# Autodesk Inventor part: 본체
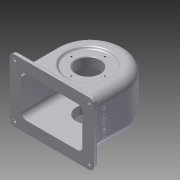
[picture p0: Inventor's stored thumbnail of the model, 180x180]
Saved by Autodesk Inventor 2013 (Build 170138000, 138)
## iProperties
Created: 2016-01
Part Number: 본체
Material: 알루미늄 6061
Document SubType Name: Modeling
Designer: dgall
Density: 2.71 g/cm^3
Mass: 810.796 g
Surface Area: 993.285 cm^2
Volume: 299.187 cm^3
Author: dgall
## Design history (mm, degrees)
sketch "스케치1"
  geometry: L1 (-57, 0)-(-57, -64); L2 (57, 0)-(57, -64); L3 (57, -64)-(-57, -64); A1 r 57 centre (0, 0) between (57, 0) and (-57, 0); 1 further point
  constraints: 6 end point, 2 point on circle, 2 tangent, 1 centre point, 1 coincident, 1 parallel, 1 perpendicular, 1 vertical
  dimensions: "d0" = 114 diameter of A1; "d2" = 64 distance of L1.start L1.end
extrude "돌출1" new body sketch "스케치1" stored distance "d3" = 77; taper "d4" = 0 deg
node "작업 평면1"
sketch "스케치2"
  geometry: L1 (57, 0)-(57, -64) reference; L2 (57, -64)-(-57, -64) reference; L3 (-57, -64)-(-57, 0) reference; L4 (-51, 0)-(-51, -64); L5 (51, 0)-(51, -64); A1 r 57 centre (0, 0) between (57, 0) and (-57, 0) reference; A2 r 51 centre (0, 0) between (51, 0) and (-51, 0); 1 further point
  constraints: 4 end point, 2 perpendicular, 2 point on circle, 2 point on line, 2 tangent, 1 centre point, 1 coincident
  dimensions: "d5" = 102 diameter of A2
extrude "돌출2" cut sketch "스케치2" stored distance "d7" = 67; taper "d8" = 0 deg
node "작업 평면2"
sketch "스케치3"
  geometry: L1 (114, 0)-(114, -77) reference; L2 (0, 0)-(114, 0) reference; L3 (0, 0)-(0, -77) reference; L4 (114, -77)-(0, -77) reference; L5 (-13, -90.5)-(127, -90.5); L6 (127, -90.5)-(127, 13.5); L7 (127, 13.5)-(-13, 13.5); L8 (-13, 13.5)-(-13, -90.5); 1 further point
  constraints: 8 end point, 2 parallel, 1 horizontal, 1 perpendicular
  dimensions: "d9" = 70 distance from line of point (57, -38.5) L6; "d10" = 140 distance of L6.end L7.end; "d11" = 52 distance from line of point (57, -38.5) L7; "d12" = 104 distance of L7.end L5.start
extrude "돌출3" join sketch "스케치3" distance "d13" = 7; taper "d14" = 0 deg
node "작업 평면3"
sketch "스케치4"
  geometry: C1 r 6 at (0, 0); 1 further point
  constraints: 1 centre point, 1 coincident
  dimensions: "d16" = 12 diameter of C1
extrude "돌출4" join sketch "스케치4" stored distance "d18" = 7; taper "d19" = 0 deg
sketch "스케치5"
  geometry: L1 (77, 121)-(0, 121) reference; L2 (-13.5, 0)-(90.5, 0) reference; L3 (0, 121)-(0, 0); L4 (0, 60.5)-(58.757, 60.5); L5 (72, 64)-(72, 115) reference; L6 (72, 0)-(72, 64) reference; L7 (77, 7)-(77, 64) reference; L8 (77, 64)-(77, 121) reference; L9 (5, 64)-(5, 0) reference; L10 (5, 115)-(5, 64) reference; L11 (5, 100.247)-(19, 88.5); L12 (19, 88.5)-(19, 60.5); L13 (19, 60.5)-(5, 60.5); L14 (5, 100.247)-(5, 60.5); 1 further point
  constraints: 12 end point, 5 point on line, 3 perpendicular, 1 collinear, 1 midpoint, 1 parallel
  dimensions: "d20" = 50 deg angle of L12 L11; "d21" = 56 diameter of L11.end L4; "d23" = 19 distance between parallel lines of L3 L12
revolve "회전1" sketch "스케치5" stored, may be unused: angle "d24" = 90 deg
sketch "스케치6"
  geometry: L1 (19, 32.5)-(19, 88.5) reference; L2 (5, 100.247)-(19, 88.5) reference; L3 (5, 20.753)-(19, 32.5) reference; L4 (19, 60.5)-(-7.161, 60.5); L5 (0, 121)-(0, 64) reference; L6 (0, 64)-(0, 7) reference; L7 (0, 97.916)-(3, 95.399); L8 (3, 95.399)-(3, 60.5); L9 (0, 97.916)-(0, 60.5); L10 (3, 60.5)-(0, 60.5); 1 further point
  constraints: 10 end point, 4 point on line, 2 parallel, 2 perpendicular, 1 midpoint
  dimensions: "d25" = 5 distance between parallel lines of L2 L7; "d28" = 3 distance between parallel lines of L5 L8
revolve "회전2" sketch "스케치6" stored, may be unused: angle "d29" = 90 deg
sketch "스케치7"
  geometry: C1 r 34.899 at (0, 0) reference; C2 r 20 at (0, 0); 1 further point
  constraints: 1 centre point, 1 coincident
  dimensions: "d30" = 40 diameter of C2
extrude "돌출5" cut sketch "스케치7" stored distance "d32" = 7; taper "d33" = 0 deg
sketch "스케치8"
  geometry: L1 (72, 40.5)-(72, 80.5) reference; L2 (72, 80.5)-(77, 80.5) reference; L3 (72, 40.5)-(77, 40.5) reference; L4 (72, 60.5)-(100.994, 60.5); L5 (77, 64)-(77, 121) reference; L6 (77, 7)-(77, 64) reference; L7 (77, 91.5)-(87, 91.5); L8 (87, 91.5)-(87, 80.5); L9 (87, 80.5)-(77, 80.5); L10 (0, 121)-(0, 64) reference; L11 (77, 91.5)-(77, 80.5); 1 further point
  constraints: 10 end point, 2 parallel, 2 perpendicular, 1 collinear, 1 midpoint, 1 point on line
  dimensions: "d37" = 87 distance between parallel lines of L10 L8; "d38" = 62 diameter of L7 L4
revolve "회전3" sketch "스케치8" stored, may be unused: angle "d39" = 90 deg
sketch "스케치9"
  geometry: L1 (90.5, -64)-(-13.5, -64) reference; L2 (38.5, -64)-(38.5, -34); L3 (14.636, -30.623)-(62.364, -30.623); L4 (62.364, -30.623)-(62.364, -37.377); L5 (62.364, -37.377)-(14.636, -37.377); L6 (14.636, -37.377)-(14.636, -30.623); L7 (14.636, -34)-(62.364, -34); L8 (38.5, -30.623)-(38.5, -37.377); 1 further point
  constraints: 6 end point, 5 midpoint, 1 perpendicular, 2 other
  dimensions: "d40" = 30 distance of L2.start L2.end; "d42" = 0 distance between parallel lines of L2 L8; "d43" = 0 distance from line of L2.end L7
extrude "돌출6" join sketch "스케치9" distance "d44" = 0.5; taper "d45" = 0 deg
fillet "모깎기1" dims "d46" = 14
fillet "모깎기2" dims "d47" = 9
chamfer "모따기1" distance "d48" = 1; stored, may be unused: second distance "d49" = 2, angle "d50" = 45 deg
fillet "모깎기3" dims "d51" = 1
fillet "모깎기4" dims "d52" = 8
sketch "스케치10"
  geometry: C1 r 2.5 at (-5, 82.5); C2 r 2.5 at (-5, -5.5); C3 r 2.5 at (119, -5.5); C4 r 2.5 at (119, 82.5); A1 r 8 centre (-5, 82.5) between (-5, 90.5) and (-13, 82.5) reference; A2 r 8 centre (-5, -5.5) between (-13, -5.5) and (-5, -13.5) reference; A3 r 8 centre (119, -5.5) between (119, -13.5) and (127, -5.5) reference; A4 r 8 centre (119, 82.5) between (127, 82.5) and (119, 90.5) reference; 1 further point
  constraints: 4 centre point, 4 coincident
  dimensions: "d53" = 5 diameter of C1; "d55" = 5 diameter of C4; "d56" = 5 diameter of C3; "d57" = 5 diameter of C2
extrude "돌출7" cut sketch "스케치10" stored distance "d58" = 0.5; taper "d59" = 0 deg
fillet "모깎기5" dims "d60" = 3
fillet "모깎기6" dims "d61" = 3
fillet "모깎기7" dims "d62" = 3
fillet "모깎기8" dims "d63" = 3
sketch "스케치11" dims "d64" = 56
  geometry: C1 r 33.5 at (0, 0) reference; C2 r 3.987 at (0, 28); 2 further points
  constraints: 1 centre point, 1 coincident, 1 vertical alignment, 2 other
hole "구멍1" sketch "스케치11" at (0, 28) diameter "d66" = 2.459; stored, may be unused: countersink angle "d70" = 90 deg, drill point angle "d72" = 118 deg; dims "d67" = 7, "d68" = 4, "d69" = 2, "d71" = 9
sketch "스케치12" dims "d76" = 48
  geometry: C1 r 21 at (0, 0) reference; C2 r 4.553 at (0, 24); 2 further points
  constraints: 1 centre point, 1 coincident, 1 vertical alignment, 2 other
hole "구멍2" sketch "스케치12" at (0, 24) diameter "d78" = 2.459; stored, may be unused: countersink angle "d82" = 90 deg, drill point angle "d84" = 118 deg; dims "d79" = 6, "d80" = 4, "d81" = 2, "d83" = 8
sketch "스케치13"
  geometry: C1 r 6 at (0, 0) reference
hole "구멍3" sketch "스케치13" at (0, 0) diameter "d88" = 4.134; stored, may be unused: countersink angle "d92" = 90 deg, drill point angle "d94" = 0 deg; dims "d89" = 20, "d90" = 4, "d91" = 2, "d93" = 20
fillet "모깎기9" dims "d95" = 3
node "솔리드1"
pattern_circular "원형 패턴1" dims angle "d74" = 360 deg
pattern_circular "원형 패턴2" dims angle "d86" = 360 deg
node "투영된 루프1"
other parameters: "d15" = 63
